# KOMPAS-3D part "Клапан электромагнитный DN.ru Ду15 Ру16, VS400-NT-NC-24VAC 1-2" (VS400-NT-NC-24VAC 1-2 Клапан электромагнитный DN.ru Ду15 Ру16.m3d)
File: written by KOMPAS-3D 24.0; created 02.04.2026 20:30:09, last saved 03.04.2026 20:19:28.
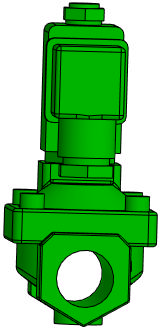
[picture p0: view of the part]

Document properties: Автор: artio; Полное имя файла: C:\Users\artio\OneDrive\Рабочий стол\Клапан электромагнитный DN.ru\VS400-NT-NC\VS400-NT-NC-24VAC 1-2 Клапан электромагнитный DN.ru Ду15 Ру16.m3d

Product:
- Body: Тело 1  | qty 1
    Масса: 1.030062
- Part/product: Клапан электромагнитный DN.ru Ду15 Ру16  | designation VS400-NT-NC-24VAC 1-2
    Масса: 0.759
    Раздел спецификации: Прочие изделия
    Примечание: D130-05631
    additional columns: ef56311e-7521-43dc-8291-0e6108b3d81d; VS400-ET-NC-220VAC 1-2; artio; c; Шероховатость не задана; Да

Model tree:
1. Операция без истории:1

Expressions: VS400-NT-NC-24VAC 1-2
